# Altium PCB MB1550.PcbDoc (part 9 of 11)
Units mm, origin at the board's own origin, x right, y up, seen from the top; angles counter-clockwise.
Board outline 154.81 x 170.69 mm, 6 copper layers (Top Layer, Signal Layer 1, Signal Layer 2, Signal Layer 3, Signal Layer 4, Bottom Layer), stack 1.49 mm thick; 810 components, 633 nets, 2973 pads, 2150 vias.
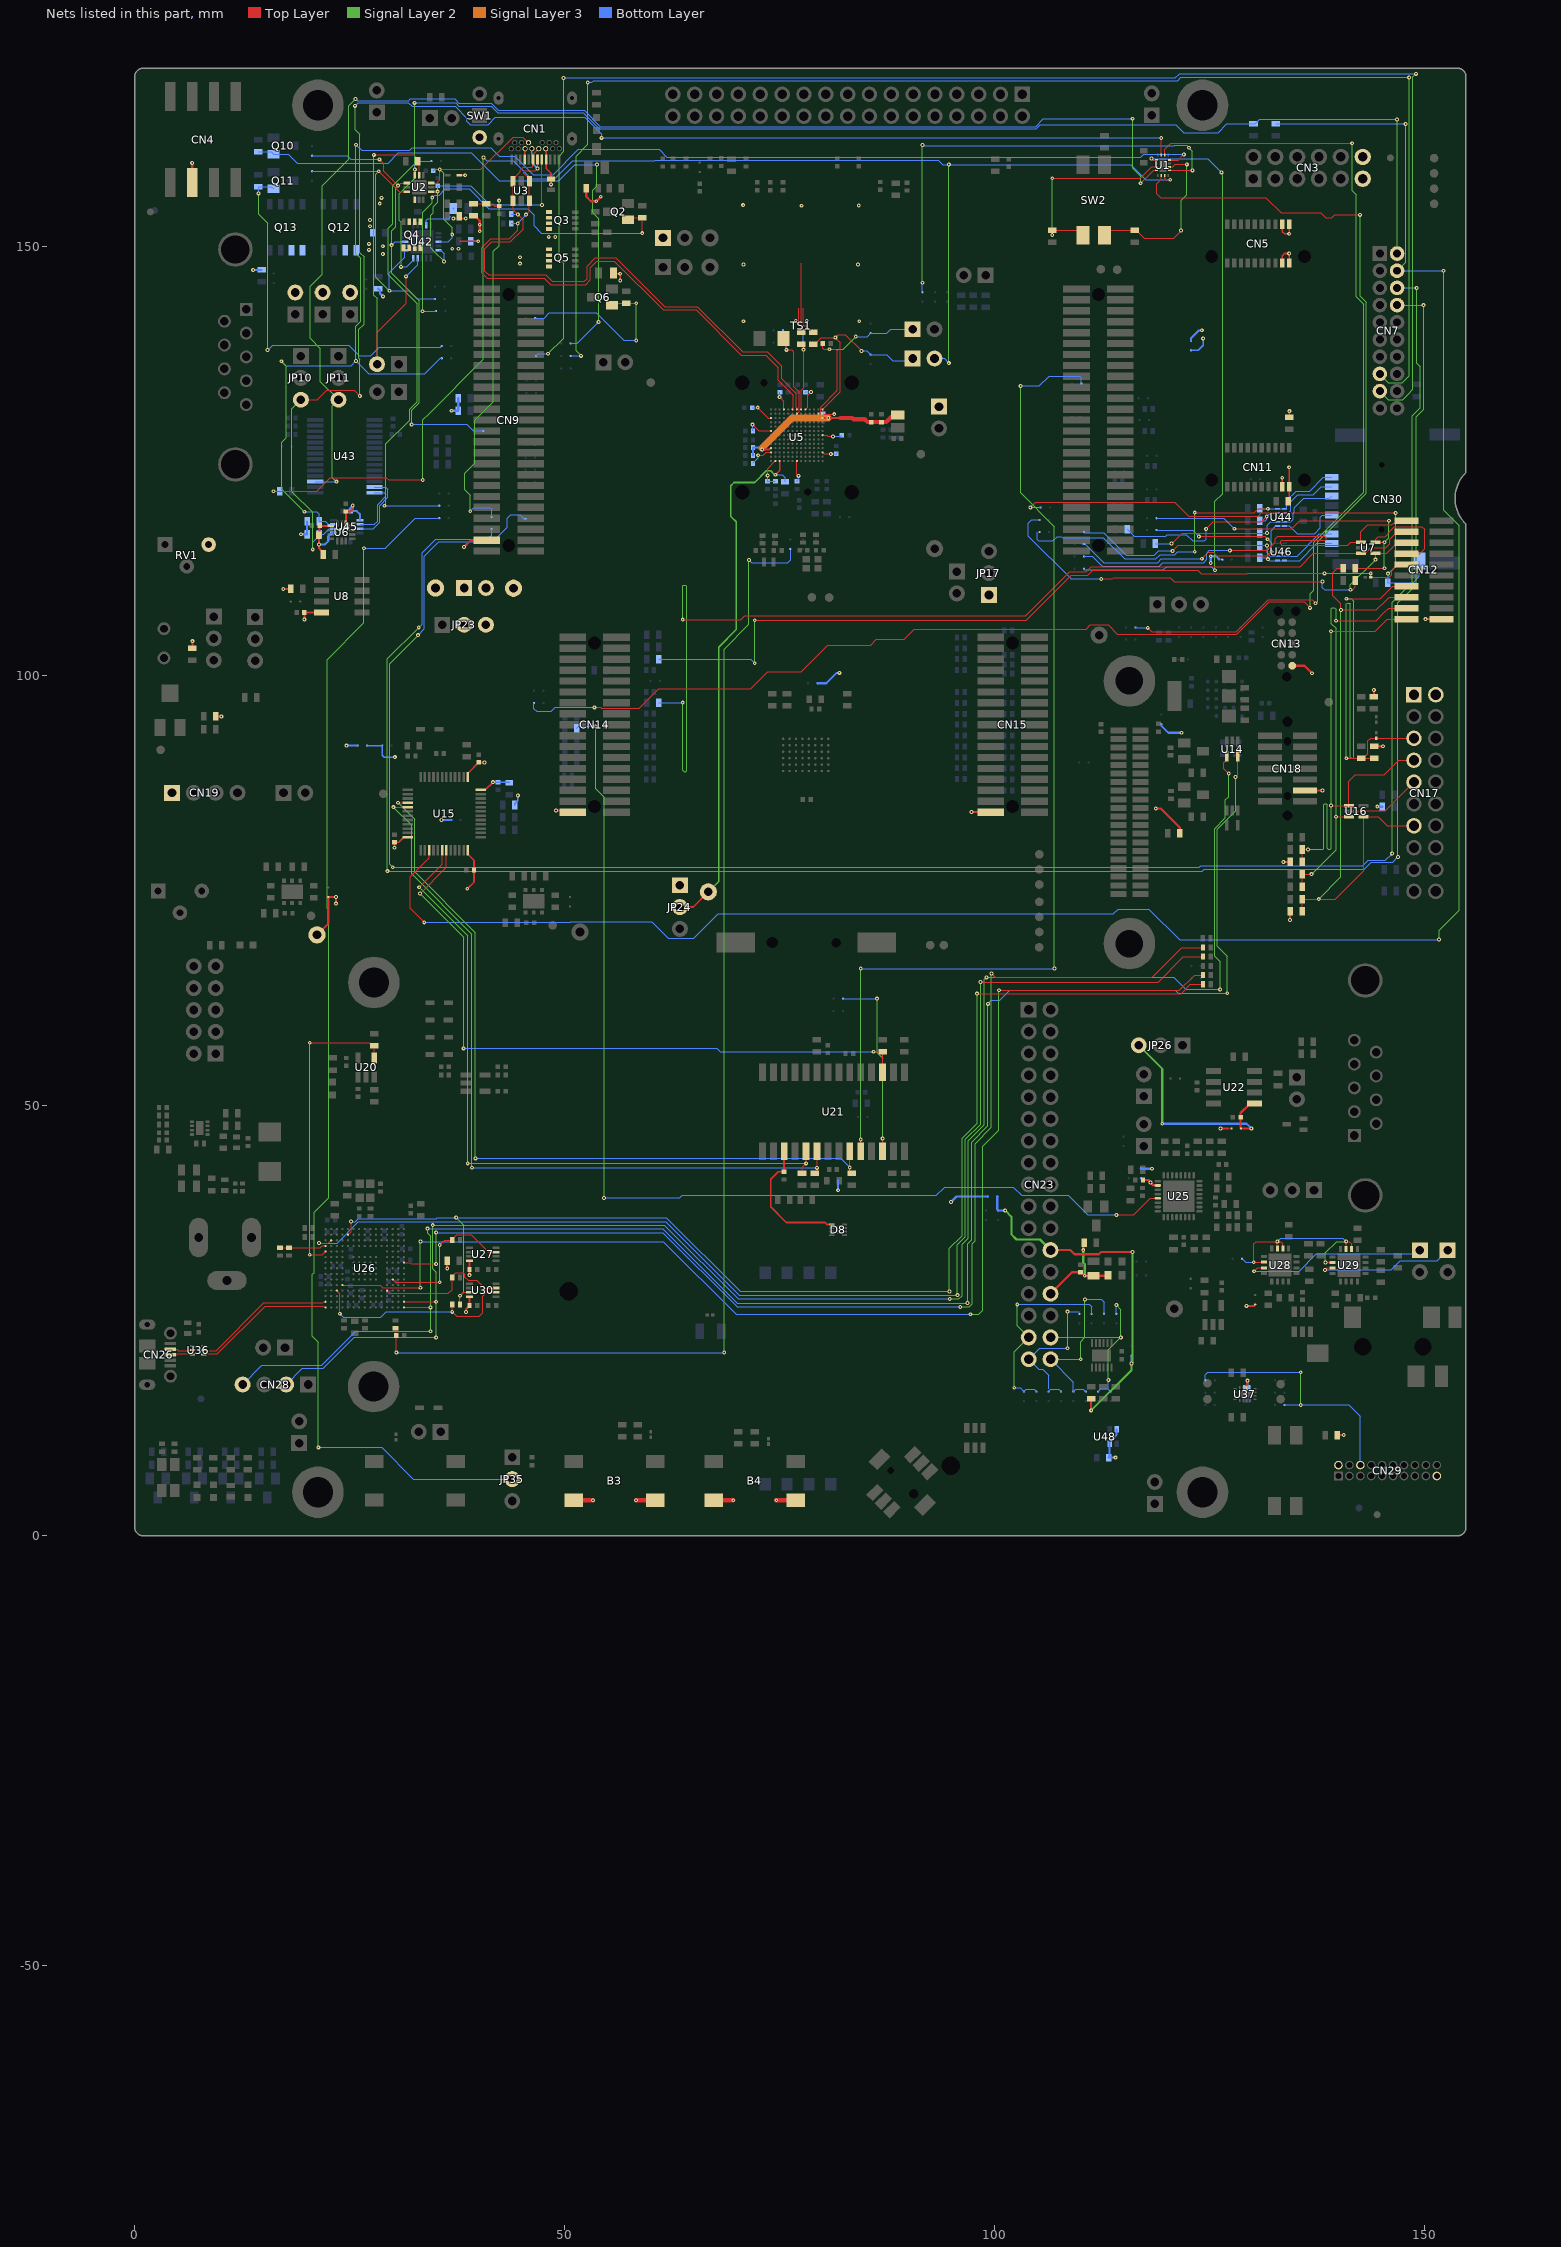
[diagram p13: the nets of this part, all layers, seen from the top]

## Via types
v1: diameter 0.45, hole 0.2, Top Layer to Bottom Layer, tented both sides, 1777 vias
v2: diameter 0.25, hole 0.1, Top Layer to Signal Layer 1, tented top, 344 vias
v3: diameter 0.25, hole 0.1, Signal Layer 1 to Signal Layer 2, 29 vias

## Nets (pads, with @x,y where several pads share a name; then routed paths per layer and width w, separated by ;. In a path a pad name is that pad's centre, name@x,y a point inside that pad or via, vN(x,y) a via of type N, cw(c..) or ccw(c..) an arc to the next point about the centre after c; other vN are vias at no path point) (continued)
SAI1_SDOUT_A: R206.1 U25.29 | length 124.6
  Top Layer w0.102: v1(114.15,37.325) 116.15,37.325 118.075,39.25 U25.29@118.975,39.25
  Signal Layer 2 w0.12: v1(53.6,94.15) 53.6,86.9 54.575,85.925 v1(54.575,39.3)
  Bottom Layer w0.102: 63.925,39.6 93.225,39.6 94.175,40.55 102.175,40.55 103.125,39.6 108.575,39.6 110.85,37.325 v1(114.15,37.325)
  Bottom Layer w0.12: R206.1@51.409,93.921 51.638,94.15 v1(53.6,94.15) ; v1(54.575,39.3) 63.375,39.3 63.675,39.6 63.925,39.6
SDCARD_DETECT: CN30.10 R174.1 SB74.1 | length 59
  Top Layer w0.12: v1(104.15,119.6) 104.76,120.21 120.965,120.21 122.599,118.576 130.629,118.576 131.017,118.963 v1(146.637,118.963)
  Signal Layer 2 w0.12: v1(145.75,111.9) 146.637,112.787 v1(146.637,118.963)
  Bottom Layer w0.12: v1(104.15,119.6) SB74.1@105.325,119.6 ; v1(145.75,111.9) 145.75,110.875 R174.1@145.725,110.85 148.671,110.85 149.398,111.577 CN30.10@149.398,113.362
SDIN0_EXT: CN29.6 SB135.2 SB146.2 | length 30.7
  Signal Layer 2 w0.12: v1(135.6,15.225) v1(135.6,19.025)
  Bottom Layer w0.12: SB135.2@124.5,18.1 124.5,18.725 124.8,19.025 v1(135.6,19.025) ; SB146.2@133.7,15.225 v1(135.6,15.225) 141.2,15.225 142.525,13.9 CN29.6@142.525,8.235
SDIO1_CLK: CN30.5 SB91.2 U44.1 U44.10 | length 35.5
  Top Layer w0.1: v1(124.1,113.625) 124.85,114.375 125.45,114.375 125.829,113.996 131.721,113.996 v1(132.175,114.45)
  Bottom Layer w0.1: 110.15,115.35 SB91.2@110.4,115.35 110.5,115.35 112.225,113.625 112.659,113.191 118.941,113.191 119.375,113.625 v1(124.1,113.625) ; v1(132.175,114.45) 132.175,116.908 132.717,117.45 U44.1@132.915,117.45 U44.10@133.735,117.45 134.273,117.45 135.177,116.547 137.197,116.547 137.875,117.225 137.875,118.475 138.112,118.712 CN30.5@139.198,118.712
SDIO1_CMD: CN30.3 R169.1 R171.1 U44.2 U44.9 | length 24.9
  Top Layer w0.1: v1(120.575,115.4) 121.8,116.625 v1(131.675,116.625)
  Bottom Layer w0.1: R171.1@118.7,115.4 v1(120.575,115.4) ; R169.1@130.825,116.625 v1(131.675,116.625) 131.675,117.533 132.092,117.95 U44.2@132.915,117.95 U44.9@133.735,117.95 134.45,117.95 134.732,118.232 134.732,118.907 134.85,119.025 134.85,119.575 135.925,120.65 138.936,120.65 CN30.3@139.198,120.912
SDIO1_D0: CN30.7 R172.1 SB84.2 U46.2 U46.9 | length 33.4
  Top Layer w0.1: v1(120.7,114.535) 121.34,115.175 v1(131.675,115.175)
  Bottom Layer w0.1: SB84.2@110.4,116.75 110.4,116.648 112.69,116.648 115.313,114.025 118.575,114.025 119.085,114.535 v1(120.7,114.535) ; R172.1@130.825,115.175 v1(131.675,115.175) 131.675,114.325 132.075,113.925 U46.2@132.915,113.925 U46.9@133.735,113.925 135.165,113.925 137.752,116.512 CN30.7@139.198,116.512
SDIO1_D1: CN30.8 R173.1 SB83.2 U46.1 U46.10 | length 25.4
  Top Layer w0.1: v1(123.75,116.225) 131.425,116.225 v1(131.75,115.9)
  Signal Layer 2 w0.102: v1(131.75,115.9) 132.225,115.425 132.225,115.125 131.779,114.679 131.779,113.596 v1(131.788,113.587)
  Bottom Layer w0.1: SB83.2@118.825,116.975 118.875,116.925 123.05,116.925 v1(123.75,116.225) ; R173.1@130.825,113.75 131.625,113.75 v1(131.788,113.587) 131.95,113.425 U46.1@132.915,113.425 U46.10@133.735,113.425 135.475,113.425 137.462,115.412 CN30.8@139.198,115.412
SDIO1_D2: CN30.1 R165.1 SB85.2 U44.5 U44.6 | length 44.6
  Top Layer w0.1: v1(123.275,118.989) 130.212,118.989 130.668,119.446 v1(131.775,119.446)
  Signal Layer 2 w0.09: v1(123.275,114.45) v1(123.275,118.989)
  Bottom Layer w0.1: 104.975,116.725 104.975,115.825 105.1,115.7 106.76,115.7 107.271,116.212 107.75,116.212 107.913,116.049 111.642,116.049 111.686,116.093 112.655,116.093 115.14,113.608 118.748,113.608 119.257,114.118 120.947,114.118 121.28,114.45 v1(123.275,114.45) ; R165.1@130.825,119.5 130.879,119.446 v1(131.775,119.446) 132.911,119.446 U44.5@132.915,119.45 U44.6@133.735,119.45 133.975,119.45 133.975,120.425 135.05,121.5 136.625,121.5 138.237,123.112 CN30.1@139.198,123.112
SDIO1_D3: CN30.2 R166.1 R168.2 U44.4 U44.7 | length 29.6
  Top Layer w0.1: 125.425,117.925 131.025,117.925
  Top Layer w0.127: v1(124.6,117.1) 125.425,117.925 ; 131.025,117.925 v1(131.65,118.55)
  Bottom Layer w0.1: R168.2@115.425,117.075 116.25,116.25 119.9,116.25 120.1,116.45 122.275,116.45 123.025,115.7 124.375,115.7 124.6,115.925 v1(124.6,117.1) ; R166.1@130.825,118.05 131.45,118.05 131.65,118.25 v1(131.65,118.55) 132.05,118.95 U44.4@132.915,118.95 U44.7@133.735,118.95 134.164,118.95 134.425,119.21 134.425,120.24 135.268,121.083 137.033,121.083 137.962,122.012 CN30.2@139.198,122.012
SHIELD: JP12.1 R22.1 SB34.1 U5.N13 | length 22.7
  Top Layer w0.08: U5.N13@80,131 82.05,133.05 82.05,136.85
  Top Layer w0.12: R22.1@78.925,138.6 79.1,138.6 79.85,139.35 v1(81.475,139.35) ; 82.05,136.85 82.05,138.775 v1(81.475,139.35) ; v1(84.525,137.796) 82.621,139.7 81.825,139.7 v1(81.475,139.35)
  Bottom Layer w0.12: v1(84.525,137.796) 85.154,137.796 SB34.1@85.575,137.375 87.48,137.375 88.17,136.685 JP12.1@90.47,136.685
SHIELD_CS: C21.1 JP9.1 SB23.1 U5.M12 | length 21.2
  Top Layer w0.08: U5.M12@79.5,130.5 79.75,130.75 79.75,131.275 81.7,133.225 81.7,136.85
  Top Layer w0.12: C21.1@80.025,138.65 80.025,138.1 80.125,138 v1(80.775,138) 81.525,138 81.7,137.825 81.7,136.85
  Signal Layer 2 w0.12: v1(80.775,138) 82.375,138 v1(83.85,139.475)
  Bottom Layer w0.12: v1(83.85,139.475) 85.175,139.475 SB23.1@85.575,139.875 87.48,139.875 87.93,140.325 JP9.1@90.47,140.325
SMARTCARD_3/5V: R75.2 U15.31 U21.3 | length 77.7
  Top Layer w0.12: v1(33.175,74.7) 36.248,77.773 U15.31@36.248,79.75
  Top Layer w0.13: v1(85.925,56.3) R75.2@87,56.3 86.965,56.265 U21.3@86.965,53.931
  Signal Layer 2 w0.12: v1(33.175,74.7) 38.25,69.625 v1(38.25,56.7)
  Bottom Layer w0.12: v1(38.25,56.7) 67.675,56.7 68.075,56.3 v1(85.925,56.3)
SMARTCARD_CLK: SB42.2 U21.24 | length 121.4
  Top Layer w0.12: U21.24@84.425,44.751 v1(84.425,46.1)
  Signal Layer 2 w0.12: v1(84.425,46.1) v1(84.425,65.976) ; v1(103.025,133.725) 103.025,121.298 106.951,117.372 106.951,116.799 v1(106.951,65.976)
  Bottom Layer w0.12: v1(84.425,65.976) v1(106.951,65.976) ; v1(103.025,133.725) 105.175,133.725 106.325,134.875 109.875,134.875 110.1,134.65 SB42.2@110.1,134
SMARTCARD_CMDVCC: R86.1 U15.30 U21.19 | length 82
  Top Layer w0.13: v1(33.075,75.425) 35.748,78.098 U15.30@35.748,79.75 ; R86.1@77.6,42.2 77.6,42.85 v1(78.075,43.325) U21.19@78.075,44.751
  Signal Layer 2 w0.13: v1(33.075,75.425) 38.725,69.775 v1(38.725,43.325)
  Bottom Layer w0.13: v1(38.725,43.325) v1(78.075,43.325)
SMARTCARD_IO: SB116.2 U21.26 | length 22
  Top Layer w0.12: U21.26@86.965,44.751 86.975,44.761 v1(86.975,46.2)
  Signal Layer 2 w0.12: v1(86.33,62.475) 86.33,56.195 86.975,55.55 v1(86.975,46.2)
  Bottom Layer w0.12: SB116.2@82.375,62.475 v1(86.33,62.475)
SMARTCARD_OFF: R88.2 U15.16 U21.23 | length 92.8
  Top Layer w0.12: v1(30.625,85.25) U15.16@31.748,85.25
  Top Layer w0.13: U21.23@83.155,44.751 v1(83.155,42.85) 83.155,42.445 R88.2@83.4,42.2
  Signal Layer 2 w0.12: v1(30.625,85.25) 32.55,83.325 32.55,77.225 39.625,70.15 v1(39.625,43.9)
  Bottom Layer w0.13: v1(39.625,43.9) 82.105,43.9 v1(83.155,42.85)
SMARTCARD_RST: R87.1 U15.17 U21.20 | length 90.2
  Top Layer w0.12: v1(30.075,84.75) U15.17@31.748,84.75
  Top Layer w0.13: R87.1@79.1,42.2 79.345,42.445 v1(79.345,42.8) U21.20@79.345,44.751
  Signal Layer 2 w0.12: v1(30.075,84.75) 32.2,82.625 32.2,77 39.22,69.98 v1(39.22,42.805)
  Bottom Layer w0.13: v1@39.22,42.8 v1(79.345,42.8)
SPI3_MISO: SB102.2 U1.6 | length 98.1
  Top Layer w0.12: v1(117.8,105.6) 118.285,105.115 128.076,105.115 131.811,108.85 136.925,108.85 v1(137.325,108.45) ; U1.6@119.375,158.225 119.375,157.775 118.825,157.225 118.825,156.1 119.3,155.625 131.55,155.625 133.325,153.85 137.927,153.85 138.477,153.3 139.2,153.3 139.525,153.625 v1(142.5,153.625)
  Signal Layer 2 w0.12: v1(137.325,108.45) 137.55,108.675 137.55,115.6 143.225,121.275 143.225,143.45 142.5,144.175 v1(142.5,153.625)
  Bottom Layer w0.12: SB102.2@116.375,105.65 116.425,105.6 v1(117.8,105.6)
SPI3_MISO2: CN7.9 SB37.2 | length 175.7
  Signal Layer 2 w0.1: CN7.9@144.8,133.128 145.8,132.128 147.453,132.128 148.1,132.775
  Signal Layer 2 w0.12: v1(48.05,137.475) 49.87,139.295 49.87,147.98 49.342,148.508 49.342,160.467 49.87,160.995 v1(49.87,169.545) ; 148.1,132.775 148.65,133.325 148.65,169.675 v1(149,170.025)
  Bottom Layer w0.12: SB37.2@46.65,137.2 46.925,137.475 v1(48.05,137.475) ; v1(49.87,169.545) 121.02,169.545 121.5,170.025 v1(149,170.025)
SPI3_MOSI: SB94.2 U1.1 | length 71.8
  Top Layer w0.12: v1(118.25,160.175) 118.425,160 U1.1@118.8,160
  Signal Layer 2 w0.12: v1(125.625,112.3) 125.625,120.3 126.5,121.175 126.5,158.45 v1(126.38,158.57)
  Bottom Layer w0.12: SB94.2@110.4,112.475 110.4,112.361 119.636,112.361 119.999,112.724 125.2,112.724 v1(125.625,112.3) ; v1(118.25,160.175) 124.775,160.175 v1(126.38,158.57)
SPI3_MOSI2: CN7.8 SB36.2 | length 168.4
  Signal Layer 2 w0.1: CN7.8@144.8,135.128 145.8,134.128 147.425,134.128 148.1,134.803
  Signal Layer 2 w0.12: v1(51.9,137.225) 51.32,137.805 51.32,160.445 52.685,161.81 v1(52.685,169.025) ; 148.1,134.803 148.205,134.908 148.205,169.595 v1(148.2,169.6)
  Bottom Layer w0.12: SB36.2@50.7,137.225 v1(51.9,137.225) ; v1(52.685,169.025) 53.175,169.025 53.375,169.225 121.275,169.225 121.65,169.6 v1(148.2,169.6)
SPI3_SCK: SB108.2 U1.14 | length 177.5
  Top Layer w0.12: v1(53.45,96.35) 54.175,96.35 54.275,96.25 58.675,96.25 60.935,98.51 71.624,98.51 73.624,100.51 77.524,100.51 80.614,103.6 85.575,103.6 86.228,104.253 89.468,104.253 90.664,105.45 110.65,105.45 111.13,105.93 113.195,105.93 114.25,104.875 128.175,104.875 131.91,108.61 135.99,108.61 v1(136.675,107.925) ; U1.14@119.775,160.575 119.775,161.25 120.475,161.95 v1(141.575,161.95)
  Signal Layer 2 w0.12: v1(136.675,107.925) 136.675,109.55 137.105,109.98 137.105,115.555 142.9,121.35 142.9,143.25 142.06,144.09 142.06,155.965 141.575,156.45 v1(141.575,161.95)
  Bottom Layer w0.12: SB108.2@46.425,96.85 46.425,96.2 46.75,95.875 48.446,95.875 48.921,96.35 v1(53.45,96.35)
SPI_NSS: SB18.2 U1.9 | length 53.7
  Top Layer w0.12: U1.9@120.35,158.8 v1(123,158.8)
  Signal Layer 2 w0.12: v1(91.6,145.725) v1(91.6,161.75) ; v1(122.6,161.425) 123,161.025 v1(123,158.8)
  Bottom Layer w0.12: SB18.2@91.6,144.625 v1(91.6,145.725) ; v1(91.6,161.75) 91.68,161.67 120.895,161.67 120.93,161.705 122.32,161.705 v1(122.6,161.425)
STLK_MCO: C108.2 R116.2 SB90.1 | length 140.6
  Top Layer w0.12: R116.2@30.35,24.15 30.425,24.075 C108.2@30.425,23.3 v1(30.425,21.325)
  Signal Layer 2 w0.12: v1(68.55,21.325) 68.55,103.125 71.425,106 v1(71.425,113.475)
  Bottom Layer w0.12: v1(30.425,21.325) v1(68.55,21.325) ; v1(71.425,113.475) 71.737,113.163 75.938,113.163 76.275,113.5 76.275,114.625
STLK_SWCLK: CN28.2 U14.4 U26.A14 | length 196.3
  Top Layer w0.09: U26.A14@31.3,27.225 v1(35.05,27.225)
  Top Layer w0.12: U14.4@126.975,90.65 126.975,90.25 126.65,89.925 126.65,89.23 v1(127.23,88.65)
  Signal Layer 2 w0.102: v1(34.66,36.135) 34.66,31.065 35.05,30.675 v1(35.05,27.225) v1(35.05,23.075)
  Signal Layer 2 w0.12: v1(94.775,27.55) 95.85,27.55 96.225,27.925 96.225,33.9 96.95,34.625 96.95,45.925 98.82,47.795 98.82,64.72 v1(99.05,64.95) ; v1(126.225,63.55) 126.225,63.972 126.23,63.977 126.23,66.745 125.58,67.395 125.58,82.241 126.831,83.492 126.831,85.583 127.23,85.982 v1(127.23,88.65)
  Bottom Layer w0.09: 24.975,22.525 25.525,23.075 v1(35.05,23.075) ; v1(34.66,36.135) 35.05,36.135
  Bottom Layer w0.102: CN28.2@17.62,17.6 19.495,19.475 21.925,19.475 24.975,22.525 ; 35.05,36.135 61.59,36.135 70.175,27.55 v1(94.775,27.55)
  Bottom Layer w0.12: v1(99.05,64.95) 120.825,64.95 122.225,63.55 v1(126.225,63.55)
STLK_SWDIO: CN28.4 U14.5 U26.A15 | length 199.4
  Top Layer w0.09: U26.A15@31.3,26.575 v1(34.4,26.575)
  Top Layer w0.12: v1(128.019,88.244) 128.275,88.5 U14.5@128.275,90.65
  Signal Layer 2 w0.1: v1(34.05,35.725) 34.05,35.2 34.4,34.85 v1(34.4,26.575) v1(34.4,23.8)
  Signal Layer 2 w0.12: v1(96.85,27.075) 96.85,33.975 97.325,34.45 97.325,45.8 99.225,47.7 v1(99.225,61.875) ; v1(127.05,63.1) 127.05,67.423 125.875,68.598 125.875,82.197 128.019,84.341 v1(128.019,88.244)
  Bottom Layer w0.09: 24.45,22.525 25.725,23.8 v1(34.4,23.8) ; v1(34.05,35.725) 35.05,35.725
  Bottom Layer w0.102: CN28.4@12.54,17.6 14.765,19.825 21.75,19.825 24.45,22.525 ; 35.05,35.725 61.4,35.725 70.05,27.075 v1(96.85,27.075)
  Bottom Layer w0.12: v1(99.225,61.875) 99.63,62.28 100.605,62.28 101.785,63.46 121.02,63.46 121.38,63.1 v1(127.05,63.1)
STLK_VCP_RX: R103.2 U26.C10 U27.3 | length 17.9
  Top Layer w0.09: U26.C10@30,29.825 30.325,29.5 35.05,29.5
  Top Layer w0.102: 35.05,29.5 v1(35.475,29.5) ; v1(35.475,33.825) 36.05,34.4 R103.2@36.925,34.4
  Top Layer w0.12: R103.2@36.925,34.4 36.925,34.525 37.425,35.025 39.15,35.025 41.175,33 U27.3@42.025,33
  Signal Layer 2 w0.102: v1(35.475,29.5) v1(35.475,33.825)
STLK_VCP_TX: R68.1 U26.A7 | length 139.1
  Top Layer w0.09: U26.A7@31.3,31.775 32,31.775 32.15,31.625 v1(35.05,31.625)
  Top Layer w0.12: v1(99.63,65.405) 100.085,64.95 118.3,64.95 121.75,68.4 R68.1@124.225,68.4
  Signal Layer 2 w0.102: v1(35.05,31.625) v1(35.05,35.275)
  Signal Layer 2 w0.12: v1(96,26.625) 97.025,26.625 97.375,26.975 97.375,33.95 97.725,34.3 97.725,45.6 99.63,47.505 v1(99.63,65.405)
  Bottom Layer w0.102: v1(35.05,35.275) 61.425,35.275 70.1,26.6 70.125,26.625 v1(96,26.625)
"STMOD+ 1-2SEL": R16.2 SW2.1 U1.3 | length 23.6
  Top Layer w0.12: v1(106.7,151.275) R16.2@106.7,151.825 109.655,151.825 SW2.1@110.255,151.225 ; v1(106.7,157.88) 116.93,157.88 118.25,159.2 U1.3@118.8,159.2
  Signal Layer 2 w0.12: v1(106.7,151.275) v1(106.7,157.88)
"STMOD+ 3-4SEL": R17.2 SW2.2 U1.10 | length 20
  Top Layer w0.12: SW2.2@112.795,151.225 113.395,151.825 R17.2@116.275,151.825 116.475,151.825 117.37,150.93 120.805,150.93 v1(121.675,151.8) ; U1.10@120.35,159.2 120.731,159.2 121.026,159.495 v1(122.355,159.495)
  Signal Layer 2 w0.12: v1(121.675,151.8) 121.675,155.3 122.355,155.98 v1(122.355,159.495)
STMOD+_ADC: CN7.13 SB79.2 | length 239.1
  Signal Layer 2 w0.12: v1(30,77.75) 29.642,78.108 29.642,101.442 v1(32.95,104.75) ; v1(146.225,79.35) 146.225,108.6 148.55,110.925 148.55,130.25 149.48,131.18 149.48,135.97 149.072,136.378 v1(149.072,145.128)
  Bottom Layer w0.1: 113.075,77.75 118.325,77.75 ; CN7.13@146.8,145.128 148.1,145.128
  Bottom Layer w0.12: v1(30,77.75) 113.075,77.75 ; v1(32.95,104.75) 33.669,105.469 33.669,113.911 35.358,115.6 41.65,115.6 43.323,117.273 43.323,118.325 43.738,118.74 44.835,118.74 45.325,118.25 SB79.2@45.475,118.25 ; 118.325,77.75 123.8,77.75 123.992,77.942 142.822,77.942 143.456,78.575 145.45,78.575 v1(146.225,79.35) ; 148.1,145.128 v1(149.072,145.128)
STMOD+_INT: CN7.11 R135.2 SB71.2 | length 189.8
  Signal Layer 2 w0.12: v1(29.025,119.8) 29.205,119.98 29.205,127.005 31.96,129.76 31.96,131.014 32.83,131.884 32.83,143.295 29.47,146.655 29.47,152.045 30,152.575 30,157 32.55,159.55 v1(32.55,166.65) ; CN7.11@146.8,149.128 v1(146.8,164.725)
  Bottom Layer w0.12: v1(29.025,119.8) SB71.2@35.412,119.8 ; v1(32.55,166.65) 37.311,166.65 37.686,166.275 41.461,166.275 42.211,165.525 52.161,165.525 54.041,163.645 104.859,163.645 105.314,164.1 121.075,164.1 121.985,163.19 125.99,163.19 127,164.2 R135.2@130.1,164.2 130.28,164.2 130.805,164.725 v1(146.8,164.725)
STMOD+_PWM: CN7.14 SB82.2 | length 235
  Signal Layer 2 w0.12: v1(29.375,77.3) 29.375,101.975 33.025,105.625 v1(33.025,105.65) ; v1(146.9,78.95) 146.9,108.525 149,110.625 149,130.151 149.875,131.026 v1(149.875,143.128)
  Bottom Layer w0.1: 113.075,77.3 118.325,77.3 ; CN7.14@146.8,143.128 148.1,143.128
  Bottom Layer w0.12: v1(29.375,77.3) 113.075,77.3 ; v1(33.025,105.65) 33.05,105.65 33.429,106.029 33.429,114.304 35.025,115.9 41.048,115.9 41.505,116.357 SB82.2@41.505,117.075 ; 118.325,77.3 124.15,77.3 124.4,77.55 143,77.55 143.785,78.335 146.285,78.335 v1(146.9,78.95) ; 148.1,143.128 v1(149.875,143.128)
STMOD+_RST: CN7.12 R134.2 U15.27 | length 249.8
  Top Layer w0.12: 32.45,77.05 32.05,76.65 ; v1(33.675,71.35) 32.05,72.975 32.05,76.65 ; U15.27@34.248,79.75 34.248,78.848 32.05,76.65
  Signal Layer 2 w0.1: CN7.12@146.8,147.128 147.8,148.128 147.8,150.3
  Signal Layer 2 w0.12: 147.8,150.3 v1(147.8,164.2) ; v1(151.68,69.345) 151.68,70.43 154.03,72.78 154.03,117.47 152.205,119.295 v1(152.205,147.128)
  Bottom Layer w0.1: CN7.12@146.8,147.128 148.1,147.128
  Bottom Layer w0.12: v1(33.675,71.35) 50.65,71.35 50.725,71.425 60.125,71.425 62.07,69.48 65.03,69.48 67.875,72.325 113.777,72.325 114.352,72.9 117.95,72.9 121.505,69.345 v1(151.68,69.345) ; R134.2@132.7,164.2 v1(147.8,164.2) ; 148.1,147.128 v1(152.205,147.128)
STPMS2_PM_CLK: SB126.1 U28.10 U28.11 U28.14 U29.10 U29.11 U29.14 | length 25.2
  Top Layer w0.12: U28.14@131.3,31.825 v1(130.125,31.825) 130.125,33.95 130.4,34.225 v1(132.875,34.225) ; U28.11@132.875,33.4 v1(132.875,34.225) ; U28.10@133.525,33.4 133.525,33.975 133.275,34.225 v1(132.875,34.225) ; v1(138.47,31.805) U29.14@139.3,31.805 ; U29.11@140.875,33.38 v1(140.875,34.225) 141.25,34.225 141.525,33.95 U29.10@141.525,33.38
  Signal Layer 2 w0.12: v1(138.47,31.805) 138.47,32.92 139.775,34.225 v1(140.875,34.225)
  Bottom Layer w0.12: SB126.1@128.775,32.225 129.175,31.825 v1(130.125,31.825) ; v1(132.875,34.225) 133.25,34.6 140.5,34.6 v1(140.875,34.225)
STPMS2_PM_DAT: JP30.1 U28.15 | length 21.6
  Top Layer w0.12: v1(130.175,30.775) 130.575,31.175 U28.15@131.3,31.175
  Bottom Layer w0.12: v1(130.175,30.775) 135.4,30.775 137.425,32.8 149.03,32.8 JP30.1@149.45,33.22
STPMS2_SG_DAT: JP31.1 U29.15 | length 16.2
  Top Layer w0.12: v1(138.425,30.925) 138.655,31.155 U29.15@139.3,31.155
  Bottom Layer w0.12: v1(138.425,30.925) 146.1,30.925 147.175,32 151.455,32 JP31.1@152.675,33.22
T_NRSTa: R69.2 U26.P3 | length 145
  Top Layer w0.1: v1(21.425,34.05) 22.525,34.05 U26.P3@22.85,34.375
  Top Layer w0.12: v1(98.36,64.4) 119,64.4 121.95,67.35 R69.2@124.225,67.35
  Signal Layer 2 w0.12: v1(95.675,28) 95.675,33.875 96.575,34.775 96.575,46.1 98.36,47.885 v1(98.36,64.4)
  Bottom Layer w0.09: v1(21.425,34.05) 23.525,34.05 26,36.525 35.05,36.525
  Bottom Layer w0.102: 35.05,36.525 61.775,36.525 70.3,28 v1(95.675,28)
T_PWR_EN: R73.2 U20.4 U26.R5 | length 35.7
  Top Layer w0.09: v1(20.35,32.7) 21.825,32.7 U26.R5@22.2,33.075
  Top Layer w0.102: v1(20.35,57.35) 27.3,57.35 27.65,57 R73.2@27.85,57
  Top Layer w0.12: U20.4@27.85,55.575 R73.2@27.85,57
  Signal Layer 2 w0.09: v1(20.35,32.7) 20.35,42.05
  Signal Layer 2 w0.102: 20.35,42.05 v1(20.35,57.35)
T_PWR_EXT: R106.2 R107.2 U26.R4 | length 5.4
  Top Layer w0.1: 19.325,33.5 21.575,33.5 21.8,33.725 U26.R4@22.2,33.725
  Top Layer w0.12: R106.2@16.875,33.5 R107.2@17.925,33.5 19.325,33.5
T_SWCLKa: R71.2 U26.M11 | length 146.1
  Top Layer w0.09: U26.M11@24.15,29.175 28.525,29.175 28.85,28.85 v1(33.225,28.85)
  Top Layer w0.12: v1(100.5,63.46) 121.485,63.46 123.25,65.225 R71.2@124.225,65.225
  Signal Layer 2 w0.09: v1(33.225,28.85) v1(33.225,34.225)
  Signal Layer 2 w0.12: v1(97.175,25.775) 97.18,25.77 98.17,25.77 98.625,26.225 98.625,45.3 100.505,47.18 100.505,62.048 100.5,62.053 v1(100.5,63.46)
  Bottom Layer w0.09: v1(33.225,34.225) 35.05,34.225
  Bottom Layer w0.102: 35.05,34.225 61.475,34.225 69.925,25.775 v1(97.175,25.775)
T_SWDIO_IN: R114.2 U26.N12 U30.2 | length 24.8
  Top Layer w0.09: U26.N12@23.5,28.525 23.85,28.175 v1(23.85,25.825)
  Top Layer w0.102: R114.2@36.925,26.9 v1(36.925,26.05) 37.425,25.55 40.075,25.55 40.475,25.95 40.475,27.85 40.95,28.325 U30.2@42.025,28.325
  Bottom Layer w0.09: v1(23.85,25.825) 24.25,25.425 28.616,25.425 29.241,26.05 35.05,26.05
  Bottom Layer w0.102: 35.05,26.05 v1(36.925,26.05)
T_SWDIOa: R72.2 R114.1 U26.L2 U30.7 | length 149.6
  Top Layer w0.09: U26.L2@24.8,35.025 25.15,35.375 v1(25.15,36.55)
  Top Layer w0.102: R114.1@37.825,26.9 v1(37.825,27.925) 38.225,28.325 U30.7@38.925,28.325
  Top Layer w0.12: v1(97.955,63.055) 121.68,63.055 122.775,64.15 R72.2@124.225,64.15
  Signal Layer 2 w0.12: v1(37.375,37.025) 38.25,36.15 38.25,28.35 v1(37.825,27.925) ; v1(94.75,28.425) 94.75,33.45 96.225,34.925 96.225,46.25 97.955,47.98 v1(97.955,63.055)
  Bottom Layer w0.09: v1(25.15,36.55) 25.625,36.55 25.975,36.9 35.05,36.9
  Bottom Layer w0.102: 35.05,36.9 35.175,37.025 v1(37.375,37.025) 61.8,37.025 70.4,28.425 v1(94.75,28.425)
T_SWOa: R113.2 U26.D12 U30.3 | length 15.7
  Top Layer w0.09: U26.D12@29.35,28.525 29.675,28.2 35.05,28.2
  Top Layer w0.102: 35.05,28.2 36.475,28.2 36.925,28.65 R113.2@36.925,30.075 36.925,30.2 37.35,30.625 38.2,30.625 38.4,30.425 38.4,30.1 38.8,29.7 39.8,29.7 40.675,28.825 U30.3@42.025,28.825
TAMPER_KEY: JP35.2 SB78.2 | length 141.7
  Signal Layer 2 w0.12: v1(21.35,10.3) 21.35,22.5 20.65,23.2 20.65,30.4 20.85,30.6 20.85,37.65 22.55,39.35 22.55,72.8 22.4,72.95 22.4,101.914 26.65,106.164 v1(26.65,114.85)
  Bottom Layer w0.12: v1(21.35,10.3) 28.7,10.3 32.4,6.6 JP35.2@43.9,6.6 ; v1(26.65,114.85) 29.15,114.85 32.65,118.35 SB78.2@35.412,118.35
TCK_SWCLK: CN12.4 CN17.9 R58.1 R61.2 U16.3 | length 56.4
  Top Layer w0.12: R61.2@135.75,75.5 R58.1@135.75,76.95 v1(136.85,76.95) ; v1(139.7,83.625) U16.3@141.2,83.625 141.65,83.625 142.325,84.3 145.4,84.3 CN17.9@148.76,87.66 ; v1(139.7,106.425) 144.35,106.425 145.332,107.407 145.805,107.88 CN12.4@147.89,107.88
  Signal Layer 2 w0.12: v1(136.85,76.95) 139.7,79.8 v1(139.7,83.625) 139.7,105.55 139.15,106.1 139.15,107.825 139.275,107.95 139.5,107.95 139.7,107.75 v1(139.7,106.425)
TDI: CN12.8 CN17.5 R46.1 R47.1 U13.1 | length 74.5
  Top Layer w0.12: v1(140.9,90.425) R46.1@142.65,90.425 R46.1@142.85,90.425 ; v1(140.9,108.975) 144.85,108.975 145.822,109.947 146.295,110.42 CN12.8@147.89,110.42 ; R47.1@144.125,90.425 R46.1@142.85,90.425 ; CN17.5@148.76,92.74 144.398,92.74 U13.1@144.375,92.763 143.713,92.763 143.4,92.45 143.4,90.975 R46.1@142.85,90.425
  Signal Layer 2 w0.12: v1(140.9,90.425) 140.9,108.375 141,108.475 141.275,108.475 141.375,108.375 141.375,90.525 141.45,90.45 141.675,90.45 141.75,90.525 141.75,108.7 141.475,108.975 v1(140.9,108.975)
TDO_SWO: CN12.6 CN17.13 R30.2 R62.1 R63.1 U16.4 | length 71.6
  Top Layer w0.12: R63.1@135.75,72.625 R62.1@135.75,74.05 v1(137.688,74.05) 139.625,74.05 142.9,77.325 U16.4@142.9,83.625 144.625,83.625 145.67,82.58 CN17.13@148.76,82.58 ; R30.2@140.55,112.525 139.825,112.525 139.325,112.025 139.325,109.35 140.275,108.4 v1(140.275,107.675) 144.4,107.675 145.402,108.677 145.875,109.15 CN12.6@147.89,109.15
  Signal Layer 2 w0.12: v1(137.688,74.05) 140.275,76.637 v1(140.275,107.675)
TKEY: R21.1 SB24.1 SB29.1 U5.H13 | length 9.9
  Top Layer w0.1: U5.H13@77.5,131 77.5,133.216 77.775,133.49 77.775,136.85
  Top Layer w0.12: R21.1@77.65,138.5 77.775,138.375 v1(77.775,137.95) 77.775,136.85
  Bottom Layer w0.12: SB24.1@77.725,140.2 SB29.1@77.725,138.775 77.775,138.725 v1(77.775,137.95)
TKEY_CS: C20.1 SB25.1 SB30.1 U5.G12 | length 12.2
  Top Layer w0.08: 76.65,136.85 76.65,133.625 77.25,133.025 77.25,130.75 U5.G12@77,130.5
  Top Layer w0.12: C20.1@75.775,139.2 v1(75.775,137.923) 76.377,137.923 76.65,137.65 76.65,136.85
  Bottom Layer w0.12: SB25.1@75.4,140.2 SB30.1@75.4,138.775 75.775,138.4 v1(75.775,137.923)
TMS_SWDIO: CN12.2 CN17.7 R54.1 R55.1 U16.1 | length 63.3
  Top Layer w0.12: R55.1@135.75,78.375 R54.1@135.75,79.825 v1(136.45,79.825) ; v1(139.125,84.925) U16.1@141.2,84.925 141.2,87.775 141.925,88.5 145.3,88.5 147,90.2 CN17.7@148.76,90.2 ; v1(139.125,105.2) 144.275,105.2 145.212,106.137 145.685,106.61 CN12.2@147.89,106.61
  Signal Layer 2 w0.12: v1(136.45,79.825) 138.15,79.825 138.25,79.925 138.25,85.025 138.375,85.15 138.55,85.15 138.675,85.025 138.675,79.95 138.8,79.825 139,79.825 139.125,79.95 v1(139.125,105.2)
TRACE_CLK: CN12.12 R184.1 U9.1 | length 96.1
  Top Layer w0.1: v1(72.1,106.475) 103.665,106.475 108.897,111.708 110.812,111.708 111.412,112.307 123.593,112.307 124.034,111.866 129.375,111.866 129.446,111.938 v1(138.363,111.938) ; v1(143.738,111.938) U9.1@143.738,111.475 145.884,111.475 146.184,111.775
  Top Layer w0.102: 146.184,111.775 146.184,112.265 146.878,112.96 CN12.12@147.89,112.96
  Signal Layer 2 w0.09: v1(72.1,101.475) v1(72.1,106.475)
  Bottom Layer w0.1: R184.1@60.95,101.925 71.65,101.925 v1(72.1,101.475) ; v1(138.363,111.938) v1(143.738,111.938)
TRACE_D0: CN12.14 R30.1 SB77.2 U7.5 | length 49.5
  Top Layer w0.1: v1(127.875,117.125) 134.575,117.125 135.5,118.05 v1(145.85,118.05) ; R30.1@141.95,112.525 v1(145.325,112.525) ; v1(145.325,115.55) U7.5@144.3,115.55 144.3,115.914 144.603,116.216 145.403,116.216 145.961,116.775 ; 149.995,114.77 149.995,116.58
  Top Layer w0.102: 145.961,116.775 145.961,116.848 146.488,117.375 149.69,117.375 149.995,117.07 149.995,116.58 ; CN12.14@147.89,114.23 149.455,114.23 149.995,114.77
  Signal Layer 2 w0.09: v1(145.325,112.525) v1(145.325,115.55) 145.85,116.075 v1(145.85,118.05)
  Bottom Layer w0.1: SB77.2@118.825,118.35 126.65,118.35 v1(127.875,117.125)
TRACE_D1: CN12.16 R31.1 SB81.2 U7.4 | length 54.6
  Top Layer w0.1: v1(112.4,111.288) 113.685,111.288 113.848,111.451 120.399,111.451 120.866,110.984 v1(138.116,110.984) ; v1(141.375,110.025) 141.625,110.025 141.95,110.35 R31.1@141.95,111.1 ; v1(144.3,113.525) U7.4@144.3,114.25 145.35,114.25
  Top Layer w0.102: 145.35,114.25 145.595,114.25 146.845,115.5 CN12.16@147.89,115.5
  Signal Layer 2 w0.09: v1(141.375,110.025) 141.375,110.6 v1(144.3,113.525)
  Bottom Layer w0.1: SB81.2@105.225,118.15 104.3,118.15 103.925,117.775 103.925,116.257 108.893,111.288 ; 108.871,111.288 108.893,111.288 ; v1(112.4,111.288) 108.893,111.288 ; v1(138.116,110.984) 138.116,110.284 138.375,110.025 v1(141.375,110.025)
TRACE_D2: CN12.18 R194.1 U7.3 | length 125.9
  Top Layer w0.1: v1(63.725,106.55) 70.475,106.55 70.95,107.025 103.625,107.025 108.724,112.125 110.639,112.125 111.239,112.724 135.514,112.724 137.04,114.25 U7.3@142.6,114.25 143.075,114.25 143.725,114.9 145.5,114.9 145.975,115.375
  Top Layer w0.102: 145.975,115.375 145.975,115.925 146.82,116.77 CN12.18@147.89,116.77
  Signal Layer 2 w0.09: v1(63.725,96.9) 63.725,89.025 63.875,88.875 64.1,88.875 64.2,88.975 64.2,110.475 64.1,110.575 63.8,110.575 63.725,110.5 v1(63.725,106.55)
  Bottom Layer w0.1: R194.1@60.95,96.9 v1(63.725,96.9)
TRACE_D3: CN12.20 SB92.2 U7.1 | length 53.8
  Top Layer w0.1: v1(127.35,114.6) 131.7,114.6 132.65,115.55 132.65,115.975 132.95,116.275 138.45,116.275 138.55,116.175 138.55,115.85 138.475,115.775 133.375,115.775 133.25,115.65 133.25,115.35 133.375,115.225 141.075,115.225 141.4,115.55 U7.1@142.6,115.55 ; U7.1@143.05,115.55 U7.1@142.6,115.55 ; 145.85,117.567 143.392,117.567 142.6,116.775 U7.1@142.6,115.55
  Top Layer w0.102: 145.85,117.567 146.167,117.567 146.386,117.786 147.636,117.786 CN12.20@147.89,118.04
  Bottom Layer w0.1: SB92.2@110.4,113.9 111.36,113.9 112.486,112.774 119.114,112.774 119.531,113.192 124.288,113.192 124.647,113.55 124.647,114.272 124.975,114.6 v1(127.35,114.6)
TS_PAD: R21.2 TS1.TKEY | length 0.7
  Top Layer w0.12: R21.2@77.5,140 TS1.TKEY@77.5,140.75
TS_SHIELD: R22.2 TS1.SHIELD | length 1.5
  Top Layer w0.102: TS1.SHIELD@77.76,140.75 77.81,140.7 78,140.7 78.7,140 78.775,140 R22.2@78.925,140
  other v1: 70.775,141.25 84.25,141.25 76.864,141.313 78.152,141.313 70.803,147.86 84.1,147.85 77.558,154.685 84.2,154.7 70.75,154.75
TSC_XN: CN23.31 SB131.2 SB142.1 SB143.1 | length 23.5
  Signal Layer 2 w0.12: v1(102.275,17.225) 102.275,21.395 CN23.31@103.96,23.08 102.625,24.415 v1(102.625,26.925)
  Bottom Layer w0.12: v1(102.275,17.225) 102.95,17.225 SB143.1@103.4,16.775 103.65,17.025 104.6,17.025 SB142.1@104.85,16.775 ; v1(102.625,26.925) 110.975,26.925 111.275,26.625 SB131.2@111.275,25.825
TSC_XP: CN23.32 SB129.2 SB136.1 SB137.1 | length 21.6
  Signal Layer 2 w0.12: v1(113.225,18.125) 113.225,21.625 v1(114.68,23.08) 114.68,26.32 v1(114.15,26.85)
  Bottom Layer w0.12: CN23.32@106.5,23.08 v1(114.68,23.08) ; SB137.1@112.025,16.775 112.35,17.1 113.15,17.1 113.225,17.025 ; v1(113.225,18.125) 113.225,17.025 ; SB136.1@113.475,16.775 113.225,17.025 ; SB129.2@114.15,25.825 v1(114.15,26.85)
TSC_YN: CN23.33 SB132.2 SB140.1 SB141.1 | length 17
  Signal Layer 2 w0.12: v1(108.475,21.825) v1(108.475,26.075)
  Bottom Layer w0.12: SB141.1@106.275,16.775 106.55,17.05 107.45,17.05 SB140.1@107.725,16.775 ; 106.275,17.125 106.275,18.7 105.6,19.375 105.125,19.375 CN23.33@103.96,20.54 105.245,21.825 v1(108.475,21.825) ; v1(108.475,26.075) 109.85,26.075
TSC_YP: CN23.34 SB130.2 SB138.1 SB139.1 | length 20.9
  Signal Layer 2 w0.12: v1(110.015,20.54) 110.015,22.605 110.5,23.09 v1(110.5,27.5)
  Bottom Layer w0.12: v1(110.015,20.54) CN23.34@106.5,20.54 109.15,17.89 SB139.1@109.15,16.775 109.45,17.075 110.3,17.075 SB138.1@110.6,16.775 ; v1(110.5,27.5) 112.375,27.5 112.725,27.15 SB130.2@112.725,25.825
UART_CTS: JP12.2 R161.1 U1.7 | length 168.1
  Top Layer w0.12: v1(16.125,121.475) 21.14,121.475 22.74,123.075 29.25,123.075 29.525,122.8 v1(33.5,122.8) ; U1.7@119.775,158.225 119.775,157.9 119.975,157.7 v1(120.425,157.7)
  Signal Layer 2 w0.12: v1(33.5,122.8) 33.5,129.775 34.225,130.5 40.55,136.825 v1(40.55,160.3) ; v1(94.675,136.375) v1(94.675,159.475)
  Bottom Layer w0.12: v1(16.125,121.475) R161.1@16.85,121.475 ; v1(40.55,160.3) 40.915,159.935 44.011,159.935 46.126,157.82 48.87,157.82 50.955,159.905 60.122,159.905 60.132,159.895 60.468,159.895 60.553,159.98 93.445,159.98 93.95,159.475 v1(94.675,159.475) 115.825,159.475 117.6,157.7 v1(120.425,157.7) ; JP12.2@93.01,136.925 94.125,136.925 v1(94.675,136.375)
UART_RTS: R167.2 SB38.2 U1.12 U45.3 | length 171.1
  Top Layer w0.12: U1.12@120.35,160 121.35,160 v1(122,160.65)
  Signal Layer 2 w0.12: v1(17.05,136.6) 17.605,136.045 17.605,127.68 17.125,127.2 17.125,121.7 v1(19.725,119.1) ; v1(25.725,136.63) 25.725,140.685 26.3,141.26 26.3,148.55 25.725,149.125 v1(25.725,161.775)
  Bottom Layer w0.12: v1(17.05,136.6) 17.555,136.095 25.19,136.095 v1(25.725,136.63) 27.2,135.155 33.73,135.155 35.525,136.95 SB38.2@35.7,136.95 ; v1(19.725,119.1) 21.175,119.1 21.45,118.825 R167.2@21.45,117.975 22.175,117.975 22.525,117.625 U45.3@23.1,117.625 ; v1(25.725,161.775) 26.375,161.125 31.975,161.125 32.255,161.405 41.42,161.405 42.41,160.415 44.21,160.415 46.325,158.3 48.671,158.3 51.603,161.232 60.968,161.232 61.858,160.342 117.017,160.342 117.325,160.65 v1(122,160.65)
UART_RTS_3V3: U43.14 U45.6 | length 7.1
  Bottom Layer w0.12: U45.6@26.2,117.625 27.862,117.625 28.237,118 28.237,119.924 29.21,120.897 29.21,121.115 29.014,121.311 U43.14@27.876,121.311
UART_RX: JP11.3 U1.4 U43.17 | length 153.6
  Top Layer w0.12: v1(116.975,157.3) 118.475,158.8 U1.4@118.8,158.8
  Signal Layer 2 w0.12: v1(23.45,122.6) 22.989,123.061 22.989,131.409 JP11.3@23.7,132.12 21.6,134.22 21.6,138.075 20.4,139.275 20.4,145.302 21.805,146.707 21.805,157.005 24.9,160.1 24.9,166.325 v1(25.675,167.1) ; v1(116.045,164.805) 116.045,159.055 116.975,158.125 v1(116.975,157.3)
  Bottom Layer w0.12: U43.17@20.976,122.611 20.987,122.6 v1(23.45,122.6) ; v1(25.675,167.1) 25.875,166.9 31.85,166.9 32.05,167.1 37.2,167.1 37.7,166.6 41.475,166.6 42.3,165.775 52.25,165.775 54.14,163.885 104.76,163.885 105.68,164.805 v1(116.045,164.805)
UART_TX: JP10.3 R170.2 U1.15 U45.2 | length 163.6
  Top Layer w0.12: JP10.3@19.325,132.12 21.245,132.12 22.35,133.225 25.505,133.225 v1(26.175,132.555) ; U1.15@119.375,160.575 v1(119.375,162.55)
  Signal Layer 2 w0.12: JP10.3@19.325,132.12 18.285,131.079 18.285,121.453 20.7,119.037 v1(20.7,114.725) ; v1(25.625,166.3) 25.625,163.525 26.175,162.975 26.175,149.225 26.675,148.725 26.675,140.925 26.05,140.3 26.05,136.925 26.175,136.8 v1(26.175,132.555)
  Bottom Layer w0.12: v1(20.7,114.725) 20.7,115.55 21.45,116.3 R170.2@21.45,116.475 21.975,116.475 22.625,117.125 U45.2@23.1,117.125 ; v1(25.625,166.3) 25.985,166.66 31.815,166.66 32.25,166.225 37.275,166.225 38.625,164.875 38.625,164.5 39.035,164.09 41.09,164.09 41.95,164.95 52.35,164.95 54.3,163 v1(54.3,162.575) v1@119.375,162.575
UART_TX_3V3: U43.13 U45.7 | length 8.5
  Bottom Layer w0.12: U45.7@26.2,117.125 27.717,117.125 28.477,117.885 28.477,119.825 29.45,120.798 29.45,121.725 29.214,121.961 U43.13@27.876,121.961
UCPD_CC1: SB12.1 SB19.2 U2.3 U42.1 | length 37.8
  Top Layer w0.12: v1(28.375,158.7) 30.75,156.325 U2.3@31.65,156.325
  Signal Layer 2 w0.12: v1(28.375,158.7) 28.045,158.37 28.045,146.379 v1(29.626,144.798)
  Bottom Layer w0.12: SB12.1@20.625,158.7 v1(28.375,158.7) ; U42.1@31.4,149.5 31.4,148.675 29.626,146.901 v1(29.626,144.798) 31.877,144.798 32.825,143.85 SB19.2@34.925,143.85
UCPD_CC1_C: C113.2 CN1.A5 U2.7 U42.15 | length 30.5
  Top Layer w0.12: U2.7@34.5,156.325 v1(35.225,156.325) ; v1@47.34,154.775 CN1.A5@47.34,160.07
  Signal Layer 2 w0.12: v1(35.225,156.325) 35.225,155.075 34.731,154.581 34.731,153.881 34.4,153.55 34.4,149.775 34.8,149.375 v1(35.975,148.2)
  Bottom Layer w0.12: v1(35.225,156.325) 35.225,156.998 C113.2@35.234,157.006 39.069,157.006 41.3,154.775 v1(47.35,154.775) ; U42.15@35.4,149.5 35.575,149.5 35.975,149.1 v1(35.975,148.2)
UCPD_CC2: SB9.2 SB52.1 U2.1 U42.3 | length 53.2
  Top Layer w0.12: v1(28.45,160.075) 28.95,159.575 28.95,158.7 v1(30.625,157.025) 30.925,157.325 U2.1@31.65,157.325
  Signal Layer 2 w0.12: v1(30.625,157.025) 30.35,156.75 30.35,152.225 29.875,151.75 v1(29.875,150.1) 29.875,146.825 33.07,143.63 33.07,131.784 32.2,130.914 v1(32.2,129.25)
  Bottom Layer w0.12: SB9.2@20.625,160.5 21.85,160.5 24.7,160.5 25.125,160.075 v1(28.45,160.075) ; v1(29.875,150.1) 30.275,150.5 U42.3@31.4,150.5 ; v1(32.2,129.25) 38.6,129.25 39.35,128.5 SB52.1@40.525,128.5
UCPD_CC2_C: C112.2 CN1.B5 U2.9 U42.13 | length 25.5
  Top Layer w0.12: U2.9@34.5,157.325 35.1,157.325 35.475,157.7 v1(35.475,158.9) 40.25,158.9 44.025,162.675 45.145,162.675 CN1.B5@45.79,162.03
  Signal Layer 2 w0.12: v1(35.475,158.9) 35.925,158.45 35.925,153.125 36.925,152.125 v1(36.925,151.325)
  Bottom Layer w0.12: C112.2@34.73,158.763 34.868,158.9 v1(35.475,158.9) ; U42.13@35.4,150.5 36.45,150.5 36.925,150.975 v1(36.925,151.325)
UCPD_DISCHARGE: Q6.1 R20.2 SB21.1 | length 20.6
  Top Layer w0.12: Q6.1@55.5,143.1 55.75,143.35 R20.2@57.175,143.35 v1(58.325,143.35)
  Signal Layer 2 w0.12: v1(58.325,139.025) v1(58.325,143.35)
  Bottom Layer w0.12: SB21.1@46.575,141.625 47.614,141.625 48.214,142.225 53.661,142.225 56.861,139.025 v1(58.325,139.025)
UCPD_FLT: JP14.2 R4.2 U2.11 U42.19 | length 46
  Top Layer w0.12: v1(27.805,160.6) 32.45,160.6 32.925,160.125 R4.2@32.925,159.875 33.075,159.725 U2.11@33.075,158.25 ; JP14.2@28.18,136.26 28.18,139.98 31.55,143.35 v1(31.55,146.475) v1@31.545,146.47
  Signal Layer 2 w0.12: v1(27.805,160.6) 27.805,144.3 28.18,143.925 JP14.2@28.18,136.26
  Bottom Layer w0.12: v1(31.55,146.475) 32.9,147.825 U42.19@32.9,148.5
UCPD_FRSCC1: Q11.1 R137.1 SB33.2 | length 42.8
  Signal Layer 2 w0.12: v1(14.4,156.125) 14.4,153.7 15.45,152.65 v1(15.45,137.9)
  Bottom Layer w0.12: v1(14.4,156.125) 14.4,156.888 R137.1@14.375,156.913 15.9,156.913 Q11.1@16.15,156.663 ; v1(15.45,137.9) 16.025,138.475 24.9,138.475 26.13,137.245 27.47,137.245 28.464,138.239 35.564,138.239 SB33.2@35.7,138.375
UCPD_FRSCC2: Q10.1 R136.2 SB31.2 | length 65.6
  Signal Layer 2 w0.12: v1(53.75,159.475) 53.75,156.975 53.262,156.487 53.262,153.863 53.95,153.175 v1(53.95,141.175)
  Bottom Layer w0.12: R136.2@14.375,160.938 15.9,160.938 Q10.1@16.15,160.688 17.862,160.688 18.9,159.65 29.475,159.65 30.65,160.825 39.125,160.825 42.37,157.58 49.297,157.58 51.192,159.475 v1(53.75,159.475) ; SB31.2@50.7,138.675 51.45,138.675 v1(53.95,141.175)
UCPD_PWR: SB10.2 SB11.2 U2.12 U42.20 | length 17.5
  Top Layer w0.12: U2.12@32.575,158.25 v1(32.575,158.9)
  Signal Layer 2 w0.12: v1(30.975,147.575) 30.975,152.8 30.775,153 30.775,156.075 32.575,157.875 v1(32.575,158.9)
  Bottom Layer w0.12: v1(30.975,147.575) 31.65,147.575 32.4,148.325 U42.20@32.4,148.5 ; v1(32.575,158.9) 32.575,159.625 SB10.2@32.825,159.875 SB11.2@34.5,159.875
UCPD_SNK01: JP7.2 Q4.1 Q4.2 Q4.3 U2.4
  other v1: 28.5,154.925 28.7,155.6
UCPD_SNK03: JP6.2 Q12.5 Q12.6
  other v1: 27.25,149.55 27.25,150.25
UCPD_SOURCE: C115.2 JP8.2 Q5.5 Q5.6 Q5.7 Q5.8 Q13.5 Q13.6
  other v1: 44.8,147.95 44.8,148.7 28.85,149.075 28.85,149.975 27.35,152.3 27.35,153.025
UCPD_SOURCE_EN: Q2.1 R13.2 SB20.1 | length 46.5
  Top Layer w0.12: Q2.1@57.375,153.05 57.625,153.3 R13.2@59.025,153.3 v1(59.025,151.5)
  Signal Layer 2 w0.12: v1(33.475,142.42) 33.475,153.925 34.6,155.05 v1(34.6,155.625)
  Bottom Layer w0.12: v1(33.475,142.42) 34.995,142.42 SB20.1@35.025,142.45 ; v1(34.6,155.625) 34.895,155.92 35.393,155.92 36.123,156.65 38.884,156.65 41.184,154.35 45.7,154.35 46.45,153.6 46.45,152.35 47.3,151.5 v1(59.025,151.5)
USB_DEV_HS_CN_N: CN26.2 U36.5 | length 2.7
  Top Layer w0.12: CN26.2@4.15,21.725 4.885,21.725 5.07,21.54 6.305,21.54 6.365,21.6 U36.5@6.725,21.6
USB_DEV_HS_CN_P: CN26.3 U36.6 | length 2.6
  Top Layer w0.12: CN26.3@4.15,21.075 4.885,21.075 4.97,21.16 6.305,21.16 6.365,21.1 U36.6@6.725,21.1
USB_DEV_HS_N: U26.R14 U36.2 | length 16.6
  Top Layer w0.12: U36.2@8.025,21.6 8.385,21.6 8.445,21.54 9.465,21.54 15.015,27.09 21.88,27.09 22.015,27.225 U26.R14@22.2,27.225
USB_DEV_HS_P: U26.R15 U36.1 | length 16.6
  Top Layer w0.12: U36.1@8.025,21.1 8.385,21.1 8.445,21.16 9.622,21.16 15.172,26.71 21.88,26.71 22.015,26.575 U26.R15@22.2,26.575
USB_FS_N: CN1.A7 CN1.B7 R139.1 U3.1 U3.6 U5.G13 | length 68.3
  Top Layer w0.12: CN1.B7@46.99,161.32 46.34,160.67 CN1.A7@46.34,160.07 46.28,160.01 46.28,159.28 46.155,159.155 45.208,159.155 44.85,158.797 44.85,158.625 44,157.775 U3.6@44,157.55 U3.1@44,155.25 44,154.225 v1(44.55,153.675) 45.18,153.045 45.18,151.968 43.687,150.475 41.54,150.475 40.725,149.66 40.725,147.075 41.145,146.655 47.77,146.655 48.525,145.9 52.274,145.9 52.595,146.221 52.595,147.657 53.568,148.63 55.945,148.63 61.625,142.95 65.43,142.95 70.7,137.68 73.557,137.68 75.225,136.012 75.225,134.537 76.94,132.822 76.94,131.245 77,131.185 U5.G13@77,131
  Bottom Layer w0.12: R139.1@43.775,153.7 43.8,153.675 v1(44.55,153.675)
USB_FS_P: CN1.A6 CN1.B6 R140.1 U3.3 U3.4 U5.F13 | length 69.5
  Top Layer w0.12: v1(44.535,152.625) 44.535,151.86 43.53,150.855 41.383,150.855 40.345,149.817 40.345,146.918 40.988,146.275 47.613,146.275 48.368,145.52 52.431,145.52 52.975,146.064 52.975,147.5 53.725,148.25 55.788,148.25 61.468,142.57 65.273,142.57 70.543,137.3 73.4,137.3 74.845,135.855 74.845,134.38 76.56,132.665 76.56,131.245 76.5,131.185 U5.F13@76.5,131 ; v1(45.5,153.65) 45.9,154.05 U3.3@45.9,155.25 U3.4@45.9,157.55 45.9,157.8 45.24,158.46 45.24,158.65 45.365,158.775 46.605,158.775 v1(46.84,159.01) CN1.A6@46.84,160.07
  Bottom Layer w0.12: R140.1@43.775,152.625 v1(44.535,152.625) 45.5,153.59 v1(45.5,153.65)
  Bottom Layer w0.155: CN1.B6@46.19,161.32 46.19,159.66 v1(46.84,159.01)
V11_COUT: C22.2 C23.2 C137.2 C138.2 L1.1 U5.A4 U5.N11 | length 21.4
  Top Layer w0.25: v1(72.975,126.325) 73.803,126.325 73.853,126.375 ; 73.875,126.375 U5.A4@74,126.5 ; U5.N11@80,130 v1(80.65,130) ; v1(80.65,130) 82.062,130
  Top Layer w0.5: 82.062,130 83.455,130 83.602,129.853 84.89,129.853 85.216,129.527 87.396,129.527 88.019,130.15 L1.1@88.525,130.15
  Signal Layer 3 w0.8: v1@72.923,126.485 76.433,129.996 v1@80.643,129.996 ; v1@80.643,130 v1(80.65,130)
  Bottom Layer w0.25: C138.2@71.9,125.65 C137.2@71.9,126.575 72.8,126.575 72.975,126.4 v1(72.975,126.325)
VBAT: C145.1 JP24.2 TP23.1 U5.C1 | length 64.7
  Top Layer w0.2: JP24.2@63.4,73.125 64.925,73.125 TP23.1@66.7,74.9 ; v1(74.5,123.4) 75,123.9 U5.C1@75,125
  Signal Layer 2 w0.2: TP23.1@66.7,74.9 67.9,76.1 67.9,103.35 ; 69.45,104.9 67.9,103.35 ; v1(74.5,123.4) 74.4,123.4 73.943,123.857 73.451,123.857 72.094,122.5 69.695,122.5 69.323,122.127 69.323,118.552 69.95,117.925 69.95,105.4 67.9,103.35
  Bottom Layer w0.1: v1(74.5,123.4) 75.3,123.4 75.625,123.075 C145.1@75.625,122.575
VBUS_SENSE: C18.2 R11.1 R12.2 SB75.2 | length 45.4
  Top Layer w0.12: R11.1@39.4,154.9 R12.2@40.9,154.9 41.625,154.9 41.875,154.65 C18.2@42.4,154.65 42.375,154.675 v1(42.375,155.275)
  Signal Layer 2 w0.12: v1(39.025,119.15) 39.025,121.023 38.4,121.648 38.4,123.561 39.55,124.711 39.55,129.736 41.714,131.899 41.714,149.366 42.375,150.027 v1(42.375,155.275)
  Bottom Layer w0.12: v1(39.025,119.15) 39.435,119.56 41.365,119.56 41.505,119.42 SB75.2@41.505,118.5
VBUSc: CN1.A4 CN1.A9 CN1.B4 CN1.B9 D2.1 Q3.5 Q3.6 Q3.7 Q3.8 Q4.5 Q4.6 Q4.7 Q4.8 R8.1 R11.2 R15.2 R19.2 R138.1 R142.2 U4.1 U42.9 | length 21.1
  Top Layer w0.2: R15.2@37.725,153.475 37.725,153.325 37.6,153.2 v1(38.5,153.2) ; D2.1@37.725,158.225 v1(38.425,158.225) ; 37.825,150.55 v1(39.95,150.55) ; CN1.A9@45.34,160.07 45.34,161.27 CN1.B4@45.39,161.32 ; CN1.B9@47.79,161.32 47.84,161.27 CN1.A4@47.84,160.07 47.84,159.01 48.4,158.45 U4.1@48.4,157.8 v1(48.4,157.175) ; R19.2@55.675,146.875 55.775,146.775 v1(56.45,146.775) ; v1(56.461,145.993) 56.461,146.786 v1@56.475,146.8
  Top Layer w0.25: R11.2@39.4,153.5 39.58,153.5 40.125,152.955 v1(40.125,152.475) v1(40.125,151.725) ; R8.1@52.5,156.7 52.5,155.75 53.05,155.2 v1(53.675,155.2) 53.695,155.2 54.2,155.705 v1(54.2,155.725)
  Bottom Layer w0.12: U42.9@33.9,152.5 33.9,153.025 34.05,153.175 36.5,153.175 36.775,153.45
  Bottom Layer w0.2: R138.1@37.05,154.375 37.05,154.325 R138.1@37.075,154.325 ; R142.2@39.1,150.55 v1(39.95,150.55)
  other v1: 36.925,149.675 37.65,149.675 48.145,151.062 48.909,151.051 37.05,153.2
VCC_CARD: C71.1 D8.1 U21.17 | length 16.1
  Top Layer w0.2: U21.17@75.535,44.751 75.5,44.716 C71.1@75.5,42.35 ; D8.1@81.05,36.2 80.55,36.2 80.3,36.45 75.765,36.45 73.96,38.256 73.96,41.46 74.85,42.35 ; 74.85,42.35 C71.1@75.5,42.35 ; 74.85,42.35 C71.1@75.5,42.35
VDD: B3.1 B3.2 B4.1 B4.2 C25.2 C26.2 C27.2 C32.2 C94.1 C104.1 C151.2 C180.2 C181.1 CN3.6 CN3.12 CN4.4 CN9.47 CN12.1 CN13.1 CN14.33 CN15.33 CN17.1 CN17.2 CN18.3 CN29.2 CN29.19 JP19.1 JP23.2 JP24.1 R29.2 R32.1 R34.1 R41.2 R43.1 R47.2 R52.2 R55.2 R63.2 R110.2 R127.2 R147.2 R149.2 R167.1 R170.1 R232.2 R245.2 R246.2 RV1.3 SB6.1 SB8.1 SB28.1 SB93.1 SB106.1 SB109.1 SB111.1 SB120.1 SB122.1 SB123.1 SW1.2 TP12.1 U6.5 U6.8 U8.8 U27.8 U30.8 U37.2 U45.1 U45.5 U48.2 U48.5 | length 90.5
  Top Layer w0.2: U37.2@129.3,17.275 129.3,17.575 129.4,17.675 v1(129.4,18.05)
  Top Layer w0.25: CN4.4@6.68,157.375 v1(6.68,159.655) ; R34.1@6.7,103.2 v1(6.7,104.049) ; R43.1@9.4,95.3 9.425,95.275 v1(10.075,95.275) ; v1(17.275,110.125) R32.1@18.125,110.125 ; v1(19.725,106.575) C32.2@19.725,107.375 19.73,107.37 U8.8@21.7,107.37 ; R29.2@21.9,114.125 21.9,114.375 21.425,114.85 v1(21.425,115.3) C27.2@21.425,116.35 21.5,116.425 C26.2@21.5,117.5 21.55,117.45 U6.8@22.8,117.45 ; U6.5@24.55,117.7 C25.2@24.55,119.125 25.076,119.125 25.35,119.399 v1(25.35,119.825) ; v1(36.35,31.1) R110.2@36.35,32 ; v1(38.297,115.002) 39.09,115.795 CN9.47@40.943,115.795 ; v1(38.525,26.025) 38.525,26.375 C104.1@38.925,26.775 U30.8@38.925,27.825 ; v1(38.925,30.325) C94.1@38.925,30.975 U27.8@38.925,32 ; v1(49.001,84.365) 50.73,84.365 CN14.33@50.925,84.17 ; v1(97.315,84.17) CN15.33@99.541,84.17 ; v1(118.741,84.584) 119.316,84.584 121.525,82.375 R52.2@121.525,81.725 ; v1(126.275,47.375) 127.2,47.375 ; v1(129.3,26.75) 130.15,26.75 SB8.1@130.3,26.9 ; v1(133.575,78.375) R55.2@134.35,78.375 ; v1(134.35,71.611) R63.2@134.35,72.625 ; CN13.1@134.61,101.185 136.041,101.185 v1(136.903,100.324) ; CN18.3@136.082,86.685 v1(138.115,86.685) ; R127.2@139.825,11.725 v1(140.6,11.725) ; R41.2@144.1,97.575 v1(144.1,98.375) ; R47.2@144.125,91.825 v1(145.151,91.825) ; v1(150.11,106.61) CN12.1@151.96,106.61
  Top Layer w0.5: B3.2@51.05,4.141 v1(53.3,4.141) ; v1(58.3,4.141) B3.1@60.55,4.141 ; B4.2@67.35,4.141 v1(69.6,4.141) ; v1(74.6,4.141) B4.1@76.85,4.141
  Bottom Layer w0.25: v1(13.773,147.222) 14.749,147.222 R246.2@14.756,147.228 ; v1(19.325,116.475) R170.1@20.05,116.475 R167.1@20.05,117.975 ; v1(21.425,115.3) 22.124,115.3 22.5,115.676 22.5,116.225 22.9,116.625 U45.1@23.1,116.625 ; v1(24.625,91.9) SB111.1@25.925,91.9 ; v1(25.35,119.825) 25.1,119.575 C151.2@25.1,119.175 25.825,119.175 26.2,118.8 U45.5@26.2,118.125 ; R245.2@28.295,145.033 28.328,145.033 28.523,144.838 28.523,144.484 v1(28.862,144.145) ; v1(36.85,130.85) R149.2@37.608,130.85 37.625,130.867 R147.2@37.625,132.3 ; SB106.1@79.4,99.15 80.409,99.15 81.624,100.365 v1(81.939,100.365) ; v1(81.8,40.2) SB122.1@81.8,41.3 ; v1(94.925,38.836) 95.564,39.475 SB123.1@99.2,39.475 ; C181.1@113.367,9.1 v1(114.075,9.1) C181.1@113.275,9.1 113.367,9.192 U48.2@113.367,10.712 113.367,10.942 114.189,11.764 U48.5@114.189,12.388 ; SB120.1@117,42.7 v1(118.3,42.7) ; SB109.1@119.384,94.421 119.384,94.221 120.204,93.4 v1(121.725,93.4) ; SB28.1@122.85,138.975 122.85,139.306 123.706,140.163 v1@124.097,140.163 ; v1(125.125,113.15) v1(125.125,113.925) 125.775,113.925 126.15,113.55 ; C180.2@129.3,17.2 129.4,17.3 v1(129.4,18.05) ; v1(144.5,84.8) R232.2@145.1,84.8
  other v1: 124.097,140.2
VDD_ADJ: JP23.3 SB3.2 TP29.1 | length 6.6
  Top Layer w0.25: TP29.1@21.2,69.9 22.5,71.2 SB3.2@22.5,74.3 v1@23.375,74.3 ; v1(23.4,73.525) 23.4,74.275 v1@23.375,74.3 ; v1(23.4,74.3) v1@23.375,74.3
VDD_BL: C92.2 C93.2 CN23.28 L4.2 R104.2 | length 11.9
  Top Layer w0.25: CN23.28@106.5,28.16 108.99,30.65 C93.2@110,30.65 110.075,30.65 v1(110.475,30.25) C92.2@111.5,30.25 113.15,30.25 L4.2@113.2,30.3 ; v1(110.3,33.225) 110.3,34 R104.2@110.4,34.1
  Signal Layer 2 w0.25: v1(110.3,33.225) 110.3,31.775 110.475,31.6 v1(110.475,30.25)
VDD_CODEC: C74.2 SB120.2 U25.26 | length 3.3
  Top Layer w0.25: C74.2@117.25,41.4 117.825,41.4 v1(118.125,41.1) 118.475,40.75 U25.26@118.975,40.75
  Bottom Layer w0.25: SB120.2@117,41.6 117.2,41.4 117.825,41.4 v1(118.125,41.1)
VDD_FDCAN: C63.1 JP26.3 SB6.2 U22.5 | length 25.9
  Top Layer w0.25: v1(129.85,47.375) SB6.2@128.65,47.375 128.6,47.425 C63.1@128.6,48.675 128.6,49.175 129.695,50.27 U22.5@130.225,50.27
  Signal Layer 2 w0.25: JP26.3@116.76,57.05 119.495,54.315 v1(119.495,47.925)
  Bottom Layer w0.25: v1(119.495,47.925) 129.3,47.925 v1(129.85,47.375)
VDD_LCD: CN23.24 R119.2 SB123.2 SB124.1 SB133.2 | length 43.3
  Top Layer w0.25: CN23.24@106.5,33.24 108.785,33.24 109.279,32.747 112.122,32.747 112.395,33.02 v1(116.02,33.02) ; v1(111.225,14.6) R119.2@111.225,15.925
  Signal Layer 2 w0.25: v1(101.225,37.85) 101.95,37.125 101.95,35.075 102.55,34.475 105.265,34.475 CN23.24@106.5,33.24 ; v1(111.225,14.6) 115.925,19.3 v1(115.925,20.05) 116.02,20.145 v1(116.02,33.02)
  Bottom Layer w0.12: 100.3,37.95 SB124.1@100.4,37.85
  Bottom Layer w0.25: 100.3,37.95 SB123.2@100.3,39.475 ; SB124.1@100.4,37.85 v1(101.225,37.85) ; v1(115.925,20.05) SB133.2@115.925,20.95
VDD_MCU: C119.2 C122.2 C123.2 C124.2 C131.2 C134.2 C136.2 C139.2 C142.2 C143.2 C144.2 JP4.1 JP16.1 JP17.1 JP19.2 SB113.2 TP13.1 U5.A3 U5.A8 U5.A11 U5.B1 U5.D13 U5.G1 U5.J13 U5.N3 U5.N7 U5.N12 | length 28.2
  Top Layer w0.08: v1(72.45,131.2) 73.65,130 U5.A11@74,130 ; v1(72.5,125.675) 73.1,125.675 73.425,126 U5.A3@74,126 ; v1(73.6,123.325) 73.6,124.1 U5.B1@74.5,125 ; v1(75,132.45) 75.5,131.95 U5.D13@75.5,131 ; U5.G1@77,125 77,123.475 v1(77.2,123.275) ; U5.J13@78,131 78.25,131.25 78.25,132.625 v1(78.65,133.025) ; U5.N3@80,126 80.175,125.825 v1(80.95,125.825) ; U5.N7@80,128 80.476,128 80.619,127.857 v1(81.197,127.857) ; U5.N12@80,130.5 80.05,130.45 v1(81.35,130.45)
  Top Layer w0.1: v1(71.85,129.225) 72.575,128.5 U5.A8@74,128.5
  Bottom Layer w0.1: C123.2@71.8,131.2 v1(72.45,131.2) ; v1(71.85,129.225) 71.85,128.6 71.925,128.525 C131.2@71.9,128.5 ; C139.2@71.9,124.725 71.9,124.8 72.5,125.4 v1(72.5,125.675) ; v1(73.6,123.325) 73.6,122.675 C144.2@73.575,122.65 C143.2@74.5,122.65 ; v1(75,132.45) 75,132.95 C122.2@75.025,132.975 ; C142.2@77,122.65 77.2,122.85 v1(77.2,123.275) ; C119.2@78,132.975 78.05,133.025 v1(78.65,133.025) ; C124.2@80.022,130.524 80.095,130.45 v1(81.35,130.45) ; v1(80.95,125.825) 81.55,125.825 81.575,125.8 C136.2@81.775,126 ; v1(81.197,127.857) 82.083,127.857 C134.2@82.225,128
  Bottom Layer w0.25: v1(35.675,83.25) SB113.2@36.8,83.25
VDD_MFX: C41.2 C44.2 C45.2 C157.2 C158.1 CN19.1 R231.1 SB110.1 SB111.2 U15.1 U15.24 U15.36 U15.48 | length 19.8
  Top Layer w0.2: v1(30.2,80.025) C44.2@30.2,80.65 30.7,80.65 31.3,81.25 U15.24@31.748,81.25 ; v1(38.675,75.25) 39.45,76.025 C45.2@39.45,77.45 39.45,78.55 38.748,79.252 U15.36@38.748,79.75 ; U15.1@38.748,88.25 38.748,88.698 C41.2@40,89.95 v1(40.675,89.95) ; U15.48@40.248,86.75 40.775,86.75 v1(41.675,87.65)
  Bottom Layer w0.2: SB111.2@27.025,91.9 SB110.1@28.775,91.9 28.775,90.798 29.013,90.559 v1(30.249,90.559) ; v1(41.675,87.65) C158.1@42.25,87.65 43.5,87.65 C157.2@43.55,87.6 ; R231.1@44.2,85 44.2,85.15 44.55,85.5 v1(44.55,86.1)
VDD_OCTOSPI_1_MOD: CN5.1 CN5.2 CN5.3 CN5.4 CN11.2 CN11.4 R23.2 R24.2 SB28.2 | length 13.9
  Top Layer w0.2: CN11.4@133.45,122.025 v1(133.45,123.05) ; CN5.4@133.45,148.025 133.45,148.875 133.7,149.125 v1(134.25,149.125) CN5.2@134.25,148.025 ; CN5.3@133.45,152.525 133.45,151.675 133.7,151.425 v1(134.25,151.425) CN5.1@134.25,152.525 ; R24.2@134.125,120.3 134.25,120.425 CN11.2@134.25,122.025 v1(134.25,124.275) ; R23.2@134.275,130.1 v1(134.275,130.8)
  Bottom Layer w0.2: SB28.2@122.85,137.875 123.675,137.875 124.25,138.45 v1(124.25,139.25)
